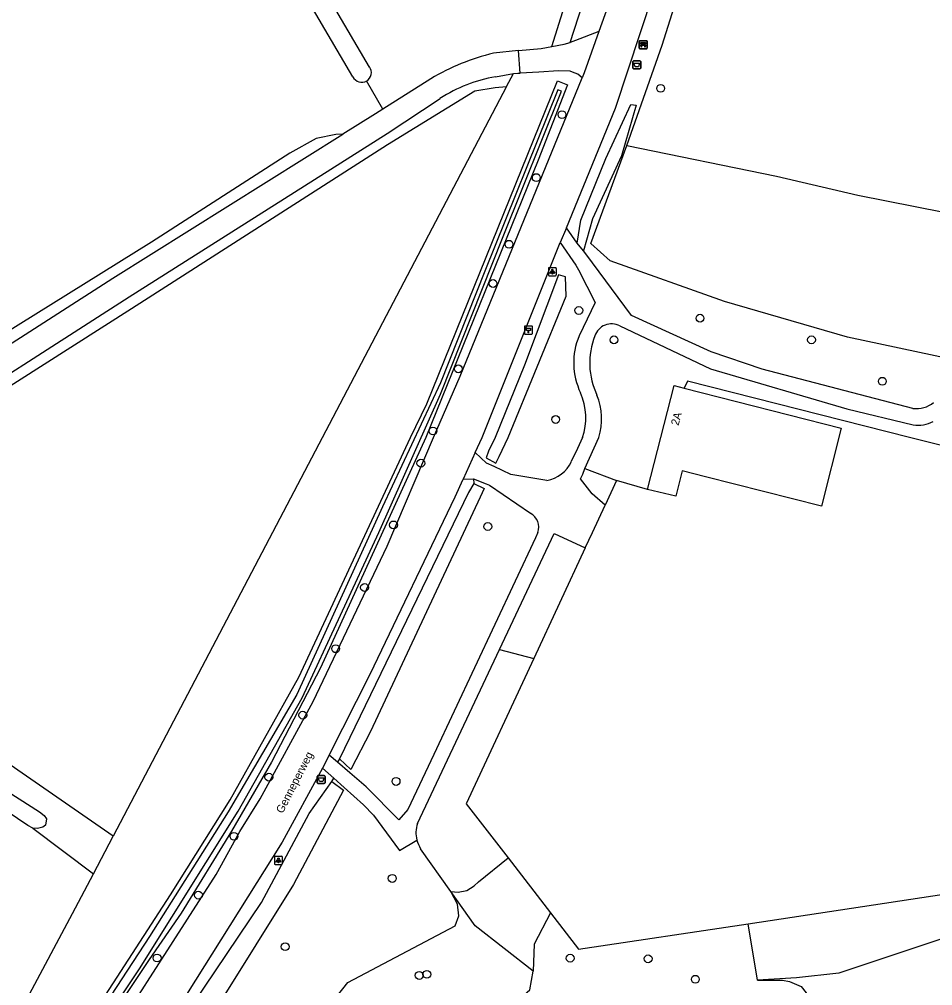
# Model space of a CAD drawing. Extents: x 160203 to 161526, y 379529 to 381797.
# Drawn here: x 160847 to 160961.1, y 380931.5 to 381052.3 of the extents above; entities that cross this region are included whole.
import ezdxf

# ---------------------------------------------------------------- set-up
doc = ezdxf.new("R2010")
doc.units = 0
for name, color, linetype in [('IMGEO_Afvalbak', 7, 'Continuous'), ('IMGEO_Bank', 7, 'Continuous'), ('IMGEO_Berm_groen', 7, 'Continuous'), ('IMGEO_Boom', 7, 'Continuous'), ('IMGEO_Bouwland', 7, 'Continuous'), ('IMGEO_Gemengd_bos', 7, 'Continuous'), ('IMGEO_Grasland_agrarisch', 7, 'Continuous'), ('IMGEO_Grasland_overig', 7, 'Continuous'), ('IMGEO_Groenvoorziening', 7, 'Continuous'), ('IMGEO_Hectometerpaal', 7, 'Continuous'), ('IMGEO_Houtwal', 7, 'Continuous'), ('IMGEO_Lichtpunt', 7, 'Continuous'), ('IMGEO_Loofbos', 7, 'Continuous'), ('IMGEO_Openbare_ruimte_label', 7, 'Continuous'), ('IMGEO_Pand', 7, 'Continuous'), ('IMGEO_Pand_nummerreeks', 7, 'Continuous'), ('IMGEO_Rijbaan_lokaal_gesloten', 7, 'Continuous'), ('IMGEO_Rijbaan_lokaal_open', 7, 'Continuous'), ('IMGEO_Terreindeel_halfverhard', 7, 'Continuous'), ('IMGEO_Voetpad_halfverhard', 7, 'Continuous'), ('IMGEO_Voetpad_onverhard', 7, 'Continuous'), ('IMGEO_Waterloop', 7, 'Continuous')]:
    doc.layers.add(name, color=color, linetype=linetype)

msp = doc.modelspace()

# ---------------------------------------------------------------- linework, layer by layer
at = {"layer": 'IMGEO_Afvalbak'}
for p, q in [((160923.64, 381046.18), (160923.64, 381046.98)), ((160923.64, 381046.98), (160923.64, 381046.18)), ((160923.74, 381047.08), (160924.53, 381047.08)), ((160924.53, 381047.08), (160923.74, 381047.08)), ((160924.53, 381046.08), (160923.74, 381046.08)), ((160923.74, 381046.08), (160924.53, 381046.08)), ((160924.63, 381046.98), (160924.63, 381046.18)), ((160924.63, 381046.18), (160924.63, 381046.98)), ((160884.18, 380956.88), (160884.18, 380957.67)), ((160884.18, 380957.67), (160884.18, 380956.88)), ((160884.28, 380957.77), (160885.07, 380957.77)), ((160885.07, 380957.77), (160884.28, 380957.77)), ((160885.07, 380956.78), (160884.28, 380956.78)), ((160884.28, 380956.78), (160885.07, 380956.78)), ((160885.17, 380957.67), (160885.17, 380956.88)), ((160885.17, 380956.88), (160885.17, 380957.67))]:
    msp.add_line(p, q, dxfattribs=at)
for points in [[(160923.78, 381046.79), (160924.49, 381046.79), (160924.34, 381046.32), (160923.93, 381046.32), (160923.78, 381046.79)], [(160884.32, 380957.49), (160885.03, 380957.49), (160884.88, 380957.02), (160884.47, 380957.02), (160884.32, 380957.49)]]:
    msp.add_lwpolyline(points, dxfattribs=at)
for centre, start, end in [((160923.74, 381046.98), 90, 180), ((160923.74, 381046.98), 90, 180), ((160923.74, 381046.18), 180, 270), ((160923.74, 381046.18), 180, 270), ((160924.53, 381046.98), 0, 90), ((160924.53, 381046.98), 360, 90), ((160924.53, 381046.18), 270, 0), ((160924.53, 381046.18), 270, 0), ((160884.28, 380957.67), 90, 180), ((160884.28, 380957.67), 90, 180), ((160884.28, 380956.88), 180, 270), ((160884.28, 380956.88), 180, 270), ((160885.07, 380957.67), 0, 90), ((160885.07, 380957.67), 360, 90), ((160885.07, 380956.88), 270, 0), ((160885.07, 380956.88), 270, 0)]:
    msp.add_arc(centre, 0.1, start, end, dxfattribs=at)
at = {"layer": 'IMGEO_Bank'}
for p, q in [((160924.44, 381048.67), (160924.44, 381049.51)), ((160924.44, 381049.51), (160924.44, 381048.67)), ((160924.51, 381049.59), (160925.36, 381049.59)), ((160925.36, 381049.59), (160924.51, 381049.59)), ((160925.37, 381048.59), (160924.52, 381048.59)), ((160924.52, 381048.59), (160925.37, 381048.59)), ((160925.14, 381048.99), (160924.74, 381048.99)), ((160924.75, 381049.1), (160924.75, 381049.2)), ((160924.79, 381049.2), (160924.79, 381049.1)), ((160925.08, 381049.21), (160924.8, 381049.21)), ((160924.8, 381049.09), (160925.08, 381049.09)), ((160925.09, 381049.1), (160925.09, 381049.2)), ((160925.13, 381049.2), (160925.13, 381049.1)), ((160925.44, 381049.52), (160925.44, 381048.68)), ((160925.44, 381048.68), (160925.44, 381049.52))]:
    msp.add_line(p, q, dxfattribs=at)
for points in [[(160924.69, 381048.99), (160924.54, 381048.99), (160924.66, 381049.09), (160924.74, 381049.09)], [(160924.74, 381049.21), (160924.66, 381049.21), (160924.66, 381049.37), (160925.22, 381049.37), (160925.22, 381049.21), (160925.14, 381049.21)], [(160924.74, 381048.98), (160924.74, 381048.78), (160924.69, 381048.78), (160924.69, 381048.98)], [(160925.14, 381049.09), (160925.22, 381049.09), (160925.33, 381048.99), (160925.19, 381048.99)], [(160925.19, 381048.98), (160925.19, 381048.78), (160925.14, 381048.78), (160925.14, 381048.98)]]:
    msp.add_lwpolyline(points, dxfattribs=at)
for centre, radius, start, end in [((160924.52, 381049.51), 0.0779, 92.4484, 184.2845), ((160924.52, 381049.51), 0.0779, 92.4484, 184.2845), ((160924.52, 381048.67), 0.0779, 182.4484, 274.2845), ((160924.52, 381048.67), 0.0779, 182.4484, 274.2845), ((160924.69, 381048.98), 0.00671, 2.8957, 87.1043), ((160924.74, 381049.2), 0.00671, 2.8957, 87.1043), ((160924.74, 381049.1), 0.00671, 272.8957, 357.1043), ((160924.74, 381048.98), 0.00671, 92.8957, 177.1043), ((160924.8, 381049.2), 0.00671, 92.8957, 177.1043), ((160924.8, 381049.1), 0.00671, 182.8957, 267.1043), ((160925.08, 381049.2), 0.00671, 2.8957, 87.1043), ((160925.08, 381049.1), 0.00671, 272.8957, 357.1043), ((160925.14, 381049.2), 0.00671, 92.8957, 177.1043), ((160925.14, 381049.1), 0.00671, 182.8957, 267.1043), ((160925.14, 381048.98), 0.00671, 2.8957, 87.1043), ((160925.19, 381048.98), 0.00671, 92.8957, 177.1043), ((160925.36, 381049.51), 0.0779, 2.4484, 94.2845), ((160925.36, 381049.51), 0.0779, 2.4484, 94.2845), ((160925.36, 381048.67), 0.0779, 272.4484, 4.2845), ((160925.36, 381048.67), 0.0779, 272.4484, 4.2845)]:
    msp.add_arc(centre, radius, start, end, dxfattribs=at)
at = {"layer": 'IMGEO_Berm_groen'}
for points in [[(160915.81, 381049.39), (160933.05, 381102.47)], [(160903.74, 380994.85), (160903.75, 380994.27)], [(160886.96, 380959.86), (160886.73, 380959.43)]]:
    msp.add_lwpolyline(points, dxfattribs=at)
at = {"layer": 'IMGEO_Boom'}
for centre in [(160927.12, 381043.64), (160914.78, 381040.36), (160911.57, 381032.49), (160908.17, 381024.16), (160906.17, 381019.25), (160916.89, 381015.89), (160932.04, 381014.92), (160921.28, 381012.21), (160945.97, 381012.22), (160901.83, 381008.6), (160954.83, 381007.04), (160913.99, 381002.27), (160898.66, 381000.82), (160897.15, 380996.8), (160893.73, 380989.09), (160905.52, 380988.89), (160890.11, 380981.27), (160886.5, 380973.62), (160882.39, 380965.32), (160878.15, 380957.57), (160894.05, 380957.04), (160873.79, 380950.18), (160893.57, 380944.92), (160869.35, 380942.83), (160880.19, 380936.39), (160864.18, 380934.97), (160915.81, 380934.95), (160925.55, 380934.88), (160896.94, 380932.8), (160897.9, 380932.93), (160931.46, 380932.32)]:
    msp.add_circle(centre, 0.489, dxfattribs=at)
at = {"layer": 'IMGEO_Bouwland'}
msp.add_lwpolyline([(160892.41, 381041.05), (160890.36, 381044.56)], dxfattribs=at)
at = {"layer": 'IMGEO_Gemengd_bos'}
for points in [[(161018.8, 381001.64), (161000, 381003.3), (160986.68, 381004.85), (160950.47, 381012.57), (160935.11, 381017.02), (160920.81, 381022.1), (160918.39, 381024.25), (160922.87, 381036.49)], [(160922.87, 381036.49), (160941.6, 381032.67), (160951.77, 381030.31), (160966.1, 381027.45), (160972.41, 381026.64), (160986.5, 381025.29), (161000, 381024.69), (161019.82, 381019.66), (161018.47, 381014.06), (161018.8, 381001.64)]]:
    msp.add_lwpolyline(points, dxfattribs=at)
at = {"layer": 'IMGEO_Grasland_agrarisch'}
msp.add_lwpolyline([(160922.87, 381036.49), (160927.32, 381049.03), (160931.34, 381061.85), (160932.29, 381064.88), (160935.38, 381074.73), (160936.75, 381077.75)], dxfattribs=at)
at = {"layer": 'IMGEO_Grasland_overig'}
for points in [[(160913.51, 381048.88), (160929.75, 381100.65), (160917.46, 381102.34), (160887.32, 381106.47), (160852.13, 381110.71)], [(160810.15, 380983.79), (160860.97, 381016.14), (160892.97, 381036.64), (160903.91, 381043.31), (160906.45, 381043.75), (160907.85, 381043.87)], [(160887.41, 381037.92), (160886.51, 381037.86), (160884.05, 381037.38), (160880.79, 381035.56), (160863.49, 381024.44), (160807.47, 380989.61)], [(160921.61, 380994.65), (160920.18, 380991.56)]]:
    msp.add_lwpolyline(points, dxfattribs=at)
at = {"layer": 'IMGEO_Groenvoorziening'}
for points in [[(160906.98, 380973.52), (160911.25, 380972.39)], [(160911.25, 380972.39), (160902.81, 380954.26), (160908.04, 380947.49)], [(160900.89, 380943.28), (160901.8, 380943.21), (160902.88, 380943.43), (160903.83, 380943.98), (160904.36, 380944.51), (160908.04, 380947.49)], [(160908.04, 380947.49), (160913.35, 380940.61)], [(160938.04, 380939.26), (160974.07, 380944.7)], [(160911.19, 380933.32), (160903.93, 380938.99), (160900.89, 380943.28)], [(160967.13, 380939), (160949.39, 380933.08), (160944.09, 380932.51), (160939.23, 380932.22)]]:
    msp.add_lwpolyline(points, dxfattribs=at)
at = {"layer": 'IMGEO_Hectometerpaal'}
for p, q in [((160910.09, 381013.86), (160910.09, 381013.02)), ((160910.09, 381013.86), (160910.09, 381013.02)), ((160911, 381013.94), (160910.16, 381013.94)), ((160911, 381013.94), (160910.16, 381013.94)), ((160911.09, 381013.03), (160911.09, 381013.87)), ((160911.09, 381013.03), (160911.09, 381013.87)), ((160910.17, 381012.94), (160911.01, 381012.94)), ((160910.17, 381012.94), (160911.01, 381012.94))]:
    msp.add_line(p, q, dxfattribs=at)
msp.add_lwpolyline([(160910.61, 381013.09), (160910.55, 381013.09), (160910.55, 381013.39), (160910.33, 381013.39), (160910.33, 381013.66), (160910.83, 381013.66), (160910.83, 381013.39), (160910.61, 381013.39), (160910.61, 381013.09)], dxfattribs=at)
for centre, start, end in [((160910.17, 381013.87), 92.4484, 184.2845), ((160910.17, 381013.87), 92.4484, 184.2845), ((160911.01, 381013.87), 2.4484, 94.2845), ((160911.01, 381013.87), 2.4484, 94.2845), ((160910.17, 381013.02), 182.4484, 274.2845), ((160910.17, 381013.02), 182.4484, 274.2845), ((160911.01, 381013.02), 272.4484, 4.2845), ((160911.01, 381013.02), 272.4484, 4.2845)]:
    msp.add_arc(centre, 0.0779, start, end, dxfattribs=at)
at = {"layer": 'IMGEO_Houtwal'}
for points in [[(160858.7, 380950.21), (160810.15, 380983.79)], [(160848.64, 380951.18), (160856.23, 380945.5)]]:
    msp.add_lwpolyline(points, dxfattribs=at)
at = {"layer": 'IMGEO_Lichtpunt'}
for p, q in [((160913.08, 381021.14), (160913.08, 381020.33)), ((160913.08, 381021.14), (160913.08, 381020.33)), ((160913.98, 381021.23), (160913.18, 381021.23)), ((160913.98, 381021.23), (160913.18, 381021.23)), ((160914.08, 381020.33), (160914.08, 381021.14)), ((160914.08, 381020.33), (160914.08, 381021.14)), ((160913.18, 381020.23), (160913.98, 381020.23)), ((160913.18, 381020.23), (160913.98, 381020.23)), ((160878.85, 380947.59), (160878.85, 380946.78)), ((160878.85, 380947.59), (160878.85, 380946.78)), ((160879.75, 380947.68), (160878.94, 380947.68)), ((160879.75, 380947.68), (160878.94, 380947.68)), ((160879.85, 380946.78), (160879.85, 380947.59)), ((160879.85, 380946.78), (160879.85, 380947.59)), ((160878.94, 380946.68), (160879.75, 380946.68)), ((160878.94, 380946.68), (160879.75, 380946.68))]:
    msp.add_line(p, q, dxfattribs=at)
for points in [[(160913.46, 381020.8), (160913.49, 381020.77), (160913.31, 381020.51), (160913.27, 381020.54), (160913.46, 381020.8)], [(160913.56, 381020.75), (160913.61, 381020.75), (160913.61, 381020.43), (160913.56, 381020.43), (160913.56, 381020.75)], [(160913.67, 381020.77), (160913.71, 381020.8), (160913.89, 381020.54), (160913.85, 381020.51), (160913.67, 381020.77)], [(160879.22, 380947.25), (160879.26, 380947.22), (160879.08, 380946.96), (160879.04, 380946.99), (160879.22, 380947.25)], [(160879.33, 380947.2), (160879.37, 380947.2), (160879.37, 380946.88), (160879.33, 380946.88), (160879.33, 380947.2)], [(160879.44, 380947.22), (160879.47, 380947.25), (160879.66, 380946.99), (160879.62, 380946.96), (160879.44, 380947.22)]]:
    msp.add_lwpolyline(points, dxfattribs=at)
for centre in [(160913.58, 381020.93), (160879.35, 380947.38)]:
    msp.add_circle(centre, 0.0994, dxfattribs=at)
for centre, start, end in [((160913.18, 381021.14), 90, 180), ((160913.18, 381021.14), 90, 180), ((160913.98, 381021.14), 0, 90), ((160913.98, 381021.14), 0, 90), ((160913.18, 381020.33), 180, 270), ((160913.18, 381020.33), 180, 270), ((160913.98, 381020.33), 270, 0), ((160913.98, 381020.33), 270, 360), ((160878.94, 380947.59), 90, 180), ((160878.94, 380947.59), 90, 180), ((160879.75, 380947.59), 0, 90), ((160879.75, 380947.59), 0, 90), ((160878.94, 380946.78), 180, 270), ((160878.94, 380946.78), 180, 270), ((160879.75, 380946.78), 270, 0), ((160879.75, 380946.78), 270, 360)]:
    msp.add_arc(centre, 0.0946, start, end, dxfattribs=at)
at = {"layer": 'IMGEO_Loofbos'}
for points in [[(160907.85, 381043.87), (160908.71, 381045.51)], [(160849.16, 380917.09), (160865.84, 380942.85), (160873.3, 380954.74), (160881.89, 380970.06), (160895.87, 381000), (160897.9, 381004.22), (160914.24, 381044.58), (160915.48, 381044.08), (160911.82, 381034.66), (160897.77, 381000), (160884.61, 380971.23), (160878.46, 380959.43), (160873.47, 380950.83), (160867.18, 380940.56), (160863.19, 380934.81), (160848.01, 380912.03)], [(160907.85, 381043.87), (160858.7, 380950.21)], [(160992.81, 380974.25), (160992.03, 380991.59), (160958.22, 381000), (160930.49, 381007.05), (160930.04, 381006.19)], [(160917.64, 380996.15), (160921.61, 380994.65)], [(160925.47, 380993.53), (160921.61, 380994.65)], [(160886.02, 380957.03), (160886.26, 380957.43)], [(160856.23, 380945.5), (160858.7, 380950.21)], [(160900.89, 380943.28), (160897.11, 380948.63)], [(160673.83, 380902.02), (160666.97, 380895.2), (160666.2, 380893.06), (160666.07, 380892.23), (160707.62, 380884.39), (160723.88, 380883.66), (160734.94, 380882.84), (160750.8, 380882.93), (160801.79, 380885.77), (160826.35, 380889.51), (160853.62, 380940.52), (160856.23, 380945.5)], [(160882.28, 380887.7), (160874.64, 380906.26), (160874.2, 380907.85), (160873.93, 380909.47), (160873.83, 380911.1), (160873.91, 380912.74), (160874.15, 380914.36), (160888.04, 380931.93), (160901.44, 380939.01), (160901.91, 380940.25), (160901.72, 380941.71), (160900.89, 380943.28)], [(160913.35, 380940.61), (160911.31, 380936.72), (160911.19, 380933.32)], [(160913.35, 380940.61), (160916.86, 380936.07), (160938.04, 380939.26)], [(160939.23, 380932.22), (160938.04, 380939.26)], [(160939.23, 380932.22), (160942.34, 380932.21), (160943.23, 380932.04), (160944.69, 380931.41), (160945.3, 380930.61), (160944.92, 380927.48), (160944.46, 380926.38), (160944.01, 380925.6), (160942.88, 380924.21), (160941.49, 380923.09), (160939.89, 380922.27), (160928.17, 380919.9), (160919.37, 380917.55), (160918.04, 380917.47), (160916.97, 380917.66), (160916.46, 380917.84), (160915.51, 380918.35), (160915.08, 380918.68), (160914.69, 380919.05), (160914.03, 380919.9), (160911.49, 380924.25), (160909.79, 380930.15), (160910.76, 380931), (160911.19, 380933.32)]]:
    msp.add_lwpolyline(points, dxfattribs=at)
msp.add_arc((160900.12, 380950.58), 3.58, 193.9543, 212.8524, dxfattribs=at)
at = {"layer": 'IMGEO_Pand'}
for points in [[(160925.47, 380993.53), (160928.79, 381006.51), (160930.04, 381006.19)], [(160930.04, 381006.19), (160949.7, 381001.19), (160947.21, 380991.42), (160932.71, 380995.11), (160929.8, 380995.85), (160929.01, 380992.69), (160925.47, 380993.53)]]:
    msp.add_lwpolyline(points, dxfattribs=at)
at = {"layer": 'IMGEO_Rijbaan_lokaal_gesloten'}
for points in [[(160915.33, 381026.22), (160921.46, 381041.16), (160927.74, 381060.12), (160928.46, 381062.22), (160929.84, 381066.2), (160933.95, 381078.05), (160934.49, 381079.74), (160949.77, 381127.68), (160952.02, 381134.89), (160959.23, 381157.7), (160964.36, 381173), (160974.47, 381200.28), (160974.68, 381200.87), (160988.22, 381238.39), (160991.59, 381248.5)], [(160940.28, 381114.91), (160930.71, 381083.28), (160930.08, 381081.4), (160925.53, 381067.76), (160919.78, 381051.79), (160919.4, 381050.73)], [(160919.4, 381050.73), (160917.55, 381045.59), (160917.29, 381044.96)], [(160854.02, 380918.09), (160871.57, 380945.42), (160874.53, 380950.78), (160877.07, 380954.85), (160883.67, 380967.04), (160892.95, 380986.45), (160898.73, 381000), (160902.08, 381007.67), (160917.29, 381044.96)], [(160915.33, 381026.22), (160914.57, 381024.37)], [(160903.94, 380998.14), (160904.79, 381000), (160914.57, 381024.37)], [(160903.94, 380998.14), (160902.43, 380994.82)], [(160885.68, 380960.32), (160890.8, 380970.43), (160901.43, 380992.62), (160902.43, 380994.82)], [(160885.68, 380960.32), (160884.85, 380958.68)], [(160884.85, 380958.68), (160879.8, 380949.47), (160867.87, 380930.41), (160854.51, 380909.81)]]:
    msp.add_lwpolyline(points, dxfattribs=at)
at = {"layer": 'IMGEO_Rijbaan_lokaal_open'}
for points in [[(160919.4, 381050.73), (160916.47, 381049.6), (160915.81, 381049.39)], [(160909.36, 381048.37), (160912.19, 381048.63), (160913.51, 381048.88)], [(160913.51, 381048.88), (160915.05, 381049.16), (160915.81, 381049.39)], [(160909.56, 381045.52), (160909.36, 381048.37)], [(160917.29, 381044.96), (160916.77, 381045.43), (160916.08, 381045.68), (160915.79, 381045.79), (160914.37, 381045.83), (160911.89, 381045.66), (160909.56, 381045.52)]]:
    msp.add_lwpolyline(points, dxfattribs=at)
at = {"layer": 'IMGEO_Terreindeel_halfverhard'}
msp.add_lwpolyline([(160917.68, 380986.21), (160911.25, 380972.39)], dxfattribs=at)
at = {"layer": 'IMGEO_Voetpad_halfverhard'}
for points in [[(160916.69, 381024.3), (160915.33, 381026.22)], [(160914.57, 381024.37), (160916.53, 381021.54), (160916.83, 381020.95), (160918.92, 381016.87), (160916.92, 381012.7)], [(160917.47, 381023.35), (160916.69, 381024.3)], [(160958.63, 381003.65), (160939.82, 381008.56), (160933.43, 381010.7), (160923.49, 381015.24), (160917.77, 381022.95), (160917.47, 381023.35)], [(160922.02, 381013.96), (160933.35, 381008.59), (160950.37, 381003.61), (160958.68, 381001.59)], [(160917.35, 381000), (160916.73, 380998.66), (160915.95, 380997.01)], [(160917.64, 380996.15), (160919.39, 381000)], [(160912.89, 380994.64), (160908.38, 380995.41), (160906.3, 380996.38), (160905.35, 380996.82), (160903.94, 380998.14)], [(160920.18, 380991.56), (160918.57, 380992.96), (160917.12, 380994.86), (160917.39, 380995.43), (160917.64, 380996.15)], [(160902.43, 380994.82), (160903.74, 380994.85)], [(160903.74, 380994.85), (160905.31, 380994.23), (160905.74, 380994.06), (160910.83, 380990.55)], [(160917.68, 380986.21), (160918.58, 380988.13), (160920.18, 380991.56)], [(160911.78, 380988.14), (160911.47, 380987.47), (160898.75, 380960.41), (160895.52, 380953.54), (160894.41, 380952.23), (160890.32, 380956.35), (160888.26, 380958.11), (160886.73, 380959.43)], [(160906.98, 380973.52), (160913.8, 380988), (160917.68, 380986.21)], [(160896.73, 380951.77), (160906.98, 380973.52)], [(160886.73, 380959.43), (160885.68, 380960.32)], [(160884.85, 380958.68), (160886.26, 380957.43)], [(160886.26, 380957.43), (160887.58, 380956.27), (160889.99, 380954.13), (160891.24, 380952.81), (160894.49, 380948.42), (160896.64, 380949.71)]]:
    msp.add_lwpolyline(points, dxfattribs=at)
for centre, radius, start, end in [((160920.99, 381012.02), 2.2, 62.1616, 162.0237), ((160924.95, 381009.35), 8.7, 157.3377, 205.5184), ((160927.43, 381009.29), 9.18, 158.2085, 205.6965), ((160910.04, 381002.47), 7.72, 341.3345, 23.9012), ((160912.03, 381002.34), 7.71, 342.3698, 22.6187), ((160959.04, 381007.15), 3.53, 263.3566, 308.5226), ((160959.32, 381005.55), 4, 260.8134, 297.9265), ((160912.09, 380998.83), 4.27, 280.7981, 334.8222), ((160909.89, 380988.78), 2, 341.2683, 62.031), ((160900.13, 380950.59), 3.6, 160.8327, 194.0431)]:
    msp.add_arc(centre, radius, start, end, dxfattribs=at)
at = {"layer": 'IMGEO_Voetpad_onverhard'}
for points in [[(160909.36, 381048.37), (160906.23, 381048.02)], [(160906.49, 381045.09), (160908.71, 381045.51)], [(160908.71, 381045.51), (160909.26, 381045.52), (160909.56, 381045.52)], [(160898.41, 381044.84), (160892.41, 381041.05)], [(160675.9, 380904.09), (160698.99, 380918.12), (160739.54, 380941.93), (160761.73, 380955.45), (160799.46, 380978.6), (160803.62, 380981.16), (160806.62, 380983), (160809.42, 380984.71), (160833.27, 381000), (160860.69, 381017.57), (160892.92, 381037.99), (160899.54, 381042.37)], [(160892.41, 381041.05), (160891.49, 381040.47), (160887.41, 381037.92)], [(160810.22, 380988.86), (160827.59, 381000), (160858.66, 381019.93), (160887.41, 381037.92)]]:
    msp.add_lwpolyline(points, dxfattribs=at)
for centre, radius, start, end in [((160912.57, 381021.21), 27.55, 103.3, 120.9303), ((160909.8, 381026.4), 18.99, 100.035, 122.7218)]:
    msp.add_arc(centre, radius, start, end, dxfattribs=at)
at = {"layer": 'IMGEO_Waterloop'}
for points in [[(160888.65, 381045.09), (160879, 381061.59), (160852.08, 381105.85), (160850.97, 381108.1), (160849.88, 381109.94), (160848.61, 381111.32), (160847.3, 381112.29), (160845.56, 381113.13)], [(160890.73, 381046.3), (160881.08, 381062.8), (160854.13, 381107.1), (160852.13, 381110.71)], [(160847.84, 380912.49), (160861.97, 380933.61), (160874.3, 380953.34), (160882.32, 380967.5), (160891.91, 380988.16), (160899.59, 381005.44), (160907.45, 381025.11), (160914.74, 381043.28), (160914.28, 381043.46), (160905.15, 381020.79), (160899.59, 381006.84), (160892.36, 380991.35), (160881.66, 380967.92), (160873.05, 380953.22), (160863.25, 380937.65), (160848.69, 380915.44)], [(160916.69, 381024.3), (160917.13, 381027.16), (160920.26, 381034.86), (160923.41, 381041.64), (160924.04, 381041.54), (160922.24, 381035.21), (160918.62, 381027.32), (160917.47, 381023.35)], [(160908.05, 381000), (160915.29, 381017.67), (160915.24, 381020.09), (160914.37, 381020.32), (160910.12, 381009.07), (160906.42, 381000.02), (160905.59, 380998.31), (160905.32, 380997.49), (160906.5, 380996.82), (160906.93, 380997.63), (160908.05, 381000)], [(160903.75, 380994.27), (160905.04, 380993.65), (160904.54, 380992.54), (160890.84, 380963.29), (160888.41, 380958.52), (160886.96, 380959.86)], [(160903.75, 380994.27), (160903.11, 380993.15), (160886.96, 380959.86)], [(160810.13, 380978.79), (160810.74, 380978.91), (160811.36, 380978.67), (160836.28, 380961.65), (160849.48, 380953.25), (160850.07, 380952.78), (160850.37, 380952.35), (160850.23, 380951.59), (160849.88, 380951.31), (160849.23, 380951.14), (160848.64, 380951.18)], [(160848.64, 380951.18), (160848.02, 380951.54), (160835.19, 380960.18), (160809.82, 380976.88)], [(160886.02, 380957.03), (160887.46, 380955.94), (160881.24, 380944.17), (160871.8, 380929.08), (160863.36, 380916.75), (160859.18, 380910.24), (160852.84, 380898.88), (160848.55, 380890.86), (160846.39, 380886.54), (160843.89, 380880.32), (160843.89, 380880.32)], [(160846.07, 380891.47), (160849.55, 380898.33), (160851.42, 380901.38), (160858.53, 380914.13), (160877.24, 380941.9), (160883.2, 380953.05), (160886.02, 380957.03)]]:
    msp.add_lwpolyline(points, dxfattribs=at)
for centre, radius, start, end in [((160889.75, 381045.6), 1.21, 300.4535, 35.8684), ((160889.77, 381045.65), 1.25, 206.775, 298.4634)]:
    msp.add_arc(centre, radius, start, end, dxfattribs=at)

# ---------------------------------------------------------------- texts
at = {"layer": 'IMGEO_Openbare_ruimte_label'}
msp.add_text('Genneperweg', height=1, rotation=62.6922, dxfattribs=at).set_placement((160879.87, 380952.96))
at = {"layer": 'IMGEO_Pand_nummerreeks'}
msp.add_text('2A', height=1, rotation=74.6392, dxfattribs=at).set_placement((160929.34, 381001.44))

doc.saveas('drawing.dxf')
